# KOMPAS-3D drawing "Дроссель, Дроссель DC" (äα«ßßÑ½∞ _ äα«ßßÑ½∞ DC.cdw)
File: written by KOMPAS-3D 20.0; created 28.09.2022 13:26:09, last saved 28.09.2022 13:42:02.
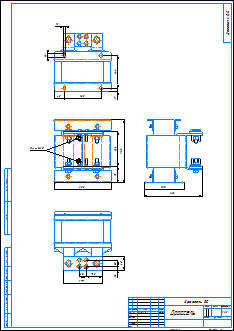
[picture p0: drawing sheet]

Sheet 1: A2, portrait

Document properties: Автор: admin; Полное имя файла: Дроссель _ Дроссель однофазный.m3d

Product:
- Part/product: Дроссель  | designation Дроссель DC
    Масса: 74.2568
    source file: Дроссель _ Дроссель однофазный.cdw
  - Component [standard]: Гайка М10-6H ГОСТ 2526-70  | qty 4  | Масса: 0.003713; Раздел спецификации: Стандартные изделия; Рассекать на разрезах: no; source file: ..\..\..\..\..\Program Files\ASCON\KOMPAS-3D v20\Libs\PARTLib\DATA\vault\Methods\Kompas\3D\PLib_Nut_OST92_900.m3d
  - Component [standard]: Шайба A.14.37 ГОСТ 11371-78  | qty 8  | Материал: АД1 ГОСТ 4784-97 (density 1000 kg/m3); Масса: 0.008612; Раздел спецификации: Стандартные изделия; Рассекать на разрезах: no; source file: ..\..\..\..\..\Program Files\ASCON\KOMPAS-3D v20\Libs\PARTLib\DATA\vault\Methods\Kompas\3D\PLib_Washer_1_712.m3d
  - Component [standard]: Шайба A 10.37 ГОСТ 10450-78  | qty 24  | Материал: АД1 ГОСТ 4784-97 (density 1000 kg/m3); Масса: 0.00210856; Раздел спецификации: Стандартные изделия; Рассекать на разрезах: no; source file: ..\..\..\..\..\Program Files\ASCON\KOMPAS-3D v20\Libs\PARTLib\DATA\vault\Methods\Kompas\3D\PLib_Washer_1_712.m3d
  - Component [standard]: Шайба 10 ГОСТ 6402-70  | qty 12  | Масса: 0.00201; Раздел спецификации: Стандартные изделия; Рассекать на разрезах: no; additional columns: 10; source file: ..\..\..\..\..\Program Files\ASCON\KOMPAS-3D v20\Libs\PARTLib\DATA\vault\Methods\Kompas\3D\PLib_Washer_2_712.m3d
  - Component [standard]: Болт М10-6gx120 (S16) ГОСТ 7798-70  | qty 4  | Масса: 0.08372; Раздел спецификации: Стандартные изделия; Рассекать на разрезах: no; source file: ..\..\..\..\..\Program Files\ASCON\KOMPAS-3D v20\Libs\PARTLib\DATA\vault\Methods\Kompas\3D\PLib_Bolt_1_900.m3d
  - Component [standard]: Гайка М10-6H ГОСТ 15522-70  | qty 8  | Масса: 0.003416; Раздел спецификации: Стандартные изделия; Рассекать на разрезах: no; source file: ..\..\..\..\..\Program Files\ASCON\KOMPAS-3D v20\Libs\PARTLib\DATA\vault\Methods\Kompas\3D\PLib_Nut_OST92_900.m3d
  - Body: Тело 2
      Масса: 70.0804
  - Body: Тело 1
      Масса: 1.08073
  - Body: Тело 5
      Масса: 0.624206
  - Component [standard]: Болт ГОСТ 32484.3 - М14 x 55 - HR  | qty 4
      Материал: Не определено (density 1000 kg/m3)
      Масса: 0.0127554
      Раздел спецификации: Стандартные изделия
      Рассекать на разрезах: no
      additional columns: ГОСТ 32484.3-2013
      source file: ..\..\..\..\..\Program Files\ASCON\KOMPAS-3D v20\Libs\PARTLib\DATA\vault\Methods\Kompas\3D\PLib_Bolt_1_ISO_1100.m3d
  - Body: Тело 4
      Масса: 0.624206
  - Component [standard]: Шайба 14 ГОСТ 6402-70  | qty 4  | Масса: 0.00448; Раздел спецификации: Стандартные изделия; Рассекать на разрезах: no; additional columns: 14; source file: ..\..\..\..\..\Program Files\ASCON\KOMPAS-3D v20\Libs\PARTLib\DATA\vault\Methods\Kompas\3D\PLib_Washer_2_712.m3d
  - Component [standard]: Болт М10x1x45 ГОСТ Р 50790-95  | qty 8  | Масса: 0.0386; Раздел спецификации: Стандартные изделия; Рассекать на разрезах: no; source file: ..\..\..\..\..\Program Files\ASCON\KOMPAS-3D v20\Libs\PARTLib\DATA\vault\Methods\Kompas\3D\PLib_Bolt_1_ISO_1100.m3d
  - Component [standard]: Гайка М14-6H ГОСТ 5915-70  | qty 4  | Масса: 0.02891; Раздел спецификации: Стандартные изделия; Рассекать на разрезах: no; source file: ..\..\..\..\..\Program Files\ASCON\KOMPAS-3D v20\Libs\PARTLib\DATA\vault\Methods\Kompas\3D\PLib_Nut_OST92_900.m3d
  - Body: Тело 3
      Масса: 0.833243

Title block, sheet 1: Наименование: Дроссель; designation: Дроссель DC; Количество листов документа: 1; Форматы листов документа: A2; stored path: C:\Users\ceh\Desktop\Уралов\Шлюз\Дроссель _ Дроссель однофазный.cdw; Разработал: Уралов Д.А.; Разработал, date: 28.09.22

Views: Проекционный вид 4
Referenced files in C:\Users\ceh\Desktop\Уралов\Шлюз\: Дроссель _ Дроссель однофазный.m3d
Referenced files in C:\Program Files\ASCON\KOMPAS-3D v20\Libs\PARTLib\DATA\vault\Methods\Kompas\3D\: PLib_Washer_1_712.m3d, PLib_Bolt_1_ISO_1100.m3d, PLib_Washer_2_712.m3d, PLib_Nut_OST92_900.m3d, PLib_Bolt_1_900.m3d
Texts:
  Шайба A.14.37 ГОСТ 11371-78
  Болт ГОСТ 32484.3 - М14 x 55 - HR
  Шайба 14 ГОСТ 6402-70
  Гайка М14-6H ГОСТ 5915-70
  Шайба A 10.37 ГОСТ 10450-78
  Шайба 10 ГОСТ 6402-70
  Гайка М10-6H ГОСТ 15522-70
  Болт М10x1x45 ГОСТ Р 50790-95
  Гайка М10-6H ГОСТ 2526-70
  Болт М10-6gx120 (S16) ГОСТ 7798-70
  Дроссель DC Дроссель
Dimensions and other numbers on the sheet: 165; 45; 146; 17; 18; 11; 1:2,5; 1; 28.09.22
